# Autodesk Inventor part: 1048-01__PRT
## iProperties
Created: 2007-03
Part Number: 1048-01__PRT
Document SubType Name: Modeling
Designer: Andy Moles
Material: Steel
Mass: 0.220829 g
Surface Area: 2.12287 cm^2
Volume: 0.028131 cm^3
Density: 7.85 g/cm^3
Author: Andy Moles
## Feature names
1. Base1
